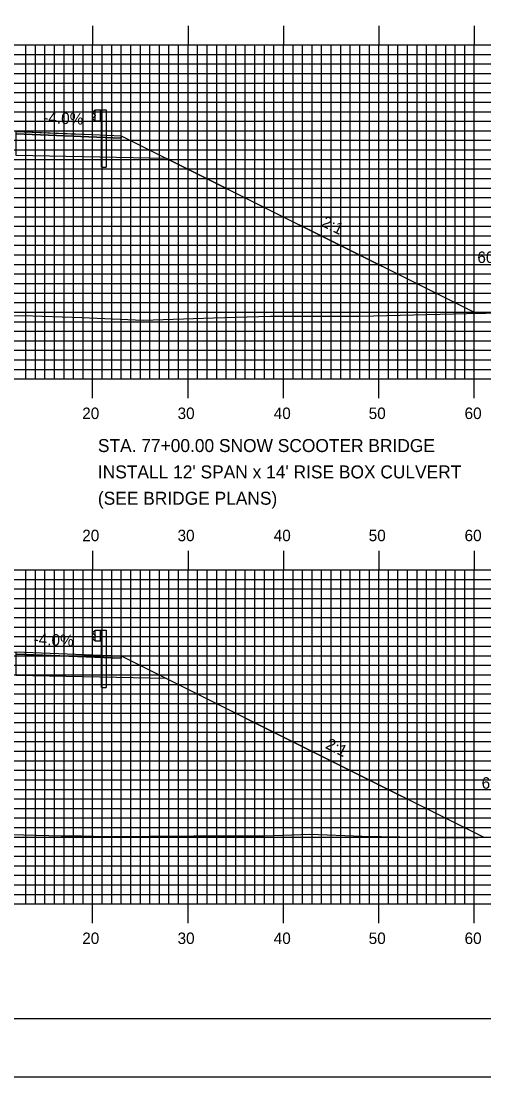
# Model space of a CAD drawing. Extents: x 1761791 to 1762134, y 442591 to 442811.
# Drawn here: x 1761969.3 to 1762017.8, y 442590.5 to 442701.2 of the extents above; entities that cross this region are included whole.
import ezdxf

# ---------------------------------------------------------------- set-up
doc = ezdxf.new("R2010")
doc.units = 0
for name, color, linetype in [('ANNOTATION', 7, 'Continuous'), ('BORDER', 7, 'Continuous'), ('D_Guardrail_Beam_Rt', 7, 'Continuous'), ('D_Roadway_Centerline', 7, 'Continuous'), ('D_Roadway_Edge_Shoulder', 7, 'Continuous'), ('D_Roadway_SlopeLines', 7, 'Continuous'), ('D_Roadway_SubGrade', 7, 'Continuous'), ('D_Text_Standard', 7, 'Continuous'), ('H_V ANNOTATION', 7, 'Continuous'), ('MAJOR', 7, 'Continuous'), ('MINOR', 7, 'Continuous'), ('PLOT BOUNDARY', 7, 'Continuous'), ('S_Roadway_Centerline', 7, 'Continuous')]:
    doc.layers.add(name, color=color, linetype=linetype)

msp = doc.modelspace()

# ---------------------------------------------------------------- linework, layer by layer
at = {"layer": 'BORDER'}
msp.add_lwpolyline([(1761807.15, 442596.67), (1762127.15, 442596.67), (1762127.15, 442806.67), (1761807.15, 442806.67)], close=True, dxfattribs=at)
at = {"layer": 'D_Guardrail_Beam_Rt'}
for p, q in [((1761976.93, 442691.75), (1761976.79, 442691.65)), ((1761977.02, 442691.77), (1761976.95, 442691.75)), ((1761977.02, 442691.85), (1761977.71, 442691.85)), ((1761977.02, 442690.68), (1761977.02, 442691.85)), ((1761977.55, 442691.85), (1761977.55, 442690.68)), ((1761977.65, 442691.85), (1761977.65, 442690.68)), ((1761977.71, 442691.85), (1761978.18, 442691.85)), ((1761977.71, 442691.85), (1761977.71, 442690.68)), ((1761978.18, 442691.85), (1761978.18, 442685.85)), ((1761976.79, 442691.5), (1761976.99, 442691.37)), ((1761976.99, 442691.17), (1761976.79, 442691.03)), ((1761976.79, 442690.89), (1761976.93, 442690.79)), ((1761976.95, 442690.78), (1761977.02, 442690.77)), ((1761977.02, 442691.3), (1761977.02, 442691.23)), ((1761977.71, 442690.68), (1761977.02, 442690.68)), ((1761977.69, 442685.85), (1761977.69, 442690.68)), ((1761977.69, 442685.85), (1761978.18, 442685.85)), ((1761977.02, 442637.35), (1761977.71, 442637.35)), ((1761977.02, 442636.18), (1761977.02, 442637.35)), ((1761977.54, 442637.35), (1761977.54, 442636.18)), ((1761977.65, 442637.35), (1761977.65, 442636.18)), ((1761977.71, 442637.35), (1761978.18, 442637.35)), ((1761977.71, 442637.35), (1761977.71, 442636.18)), ((1761978.18, 442637.35), (1761978.18, 442631.35)), ((1761976.93, 442637.25), (1761976.79, 442637.15)), ((1761976.79, 442637), (1761976.99, 442636.87)), ((1761976.99, 442636.67), (1761976.79, 442636.53)), ((1761976.79, 442636.39), (1761976.93, 442636.29)), ((1761977.02, 442637.27), (1761976.95, 442637.25)), ((1761976.95, 442636.28), (1761977.02, 442636.27)), ((1761977.02, 442636.8), (1761977.02, 442636.73)), ((1761977.71, 442636.18), (1761977.02, 442636.18)), ((1761977.69, 442631.35), (1761977.69, 442636.18)), ((1761977.69, 442631.35), (1761978.18, 442631.35))]:
    msp.add_line(p, q, dxfattribs=at)
for centre, major_axis, start_param, end_param in [((1761976.84, 442691.57), (-0.0877, 0), 5.323254, 7.243116), ((1761976.96, 442691.71), (-0.0417, 0), 4.907132, 5.323254), ((1761976.84, 442690.96), (-0.0877, 0), 5.323254, 7.243116), ((1761976.96, 442690.82), (-0.0417, 0), 0.959931, 1.376053), ((1761976.94, 442691.3), (0.0789, 0), 0, 0.959931), ((1761976.94, 442691.23), (0.0789, 0), 5.323254, 6.283185), ((1761976.84, 442637.07), (-0.0877, 0), 5.323254, 7.243116), ((1761976.84, 442636.46), (-0.0877, 0), 5.323254, 7.243116), ((1761976.96, 442637.21), (-0.0417, 0), 4.907132, 5.323254), ((1761976.96, 442636.32), (-0.0417, 0), 0.959931, 1.376053), ((1761976.94, 442636.8), (0.0789, 0), 0, 0.959931), ((1761976.94, 442636.73), (0.0789, 0), 5.323254, 6.283185)]:
    msp.add_ellipse(centre, major_axis=major_axis, ratio=0.995501, start_param=start_param, end_param=end_param, dxfattribs=at)
at = {"layer": 'D_Roadway_Centerline'}
for points in [[(1761968.76, 442689.59), (1761974.5, 442689.36), (1761976.75, 442689.27), (1761979.75, 442689.15), (1761984.5, 442686.77), (1761984.5, 442686.77), (1761984.51, 442686.77), (1761997.36, 442680.34), (1762016.93, 442670.56), (1762016.94, 442670.55)], [(1761899.44, 442616.62), (1761899.44, 442616.63), (1761910.41, 442622.11), (1761928.44, 442631.13), (1761928.46, 442631.14), (1761933.75, 442633.78), (1761935.04, 442633.83), (1761936.75, 442633.9), (1761944.75, 442634.22), (1761956.75, 442634.66), (1761956.75, 442634.66), (1761968.75, 442635.09), (1761968.75, 442635.09), (1761968.75, 442635.09), (1761976.75, 442634.77), (1761976.75, 442634.77), (1761979.75, 442634.65), (1761984.5, 442632.27), (1761984.5, 442632.27), (1762000.79, 442624.13), (1762017.75, 442615.65)]]:
    msp.add_lwpolyline(points, dxfattribs=at)
at = {"layer": 'D_Roadway_Edge_Shoulder'}
for points in [[(1761968.75, 442689.59), (1761976.75, 442689.27), (1761976.75, 442689.27), (1761979.75, 442689.15), (1761979.75, 442688.9), (1761968.75, 442689.34)], [(1761968.75, 442635.09), (1761976.75, 442634.77), (1761976.75, 442634.77), (1761979.75, 442634.65), (1761979.75, 442634.4), (1761968.75, 442634.84)]]:
    msp.add_lwpolyline(points, close=True, dxfattribs=at)
at = {"layer": 'D_Roadway_SlopeLines'}
for points in [[(1761979.75, 442689.15), (1762016.94, 442670.55)], [(1761979.75, 442634.65), (1762017.75, 442615.65)]]:
    msp.add_lwpolyline(points, dxfattribs=at)
at = {"layer": 'D_Roadway_SubGrade'}
for points in [[(1761968.75, 442688.92), (1761968.75, 442689.34), (1761979.75, 442688.9), (1761979.75, 442689.15), (1761984.5, 442686.77), (1761968.75, 442687.09)], [(1761968.75, 442634.42), (1761968.75, 442634.84), (1761979.75, 442634.4), (1761979.75, 442634.65), (1761984.5, 442632.27), (1761968.75, 442632.59)]]:
    msp.add_lwpolyline(points, close=True, dxfattribs=at)
at = {"layer": 'MAJOR'}
for p, q in [((1761976.75, 442700.67), (1761976.75, 442698.67)), ((1761986.75, 442700.67), (1761986.75, 442698.67)), ((1761996.75, 442700.67), (1761996.75, 442698.67)), ((1762006.75, 442700.67), (1762006.75, 442698.67)), ((1762016.75, 442700.67), (1762016.75, 442698.67)), ((1761816.75, 442698.67), (1762096.75, 442698.67)), ((1761816.75, 442698.67), (1762096.75, 442698.67)), ((1761976.75, 442663.67), (1761976.75, 442698.67)), ((1761986.75, 442663.67), (1761986.75, 442698.67)), ((1761996.75, 442663.67), (1761996.75, 442698.67)), ((1762006.75, 442663.67), (1762006.75, 442698.67)), ((1762016.75, 442663.67), (1762016.75, 442698.67)), ((1761816.75, 442693.67), (1762096.75, 442693.67)), ((1761816.75, 442688.67), (1762096.75, 442688.67)), ((1761816.75, 442683.67), (1762096.75, 442683.67)), ((1761816.75, 442678.67), (1762096.75, 442678.67)), ((1761816.75, 442673.67), (1762096.75, 442673.67)), ((1761816.75, 442668.67), (1762096.75, 442668.67)), ((1761816.75, 442663.67), (1762096.75, 442663.67)), ((1761816.75, 442663.67), (1762096.75, 442663.67)), ((1761976.75, 442661.66), (1761976.75, 442663.67)), ((1761986.75, 442661.66), (1761986.75, 442663.67)), ((1761996.75, 442661.66), (1761996.75, 442663.67)), ((1762006.75, 442661.66), (1762006.75, 442663.67)), ((1762016.75, 442661.66), (1762016.75, 442663.67)), ((1761976.75, 442645.67), (1761976.75, 442643.67)), ((1761986.75, 442645.67), (1761986.75, 442643.67)), ((1761996.75, 442645.67), (1761996.75, 442643.67)), ((1762006.75, 442645.67), (1762006.75, 442643.67)), ((1762016.75, 442645.67), (1762016.75, 442643.67)), ((1761816.75, 442643.67), (1762096.75, 442643.67)), ((1761816.75, 442643.67), (1762096.75, 442643.67)), ((1761976.75, 442608.67), (1761976.75, 442643.67)), ((1761986.75, 442608.67), (1761986.75, 442643.67)), ((1761996.75, 442608.67), (1761996.75, 442643.67)), ((1762006.75, 442608.67), (1762006.75, 442643.67)), ((1762016.75, 442608.67), (1762016.75, 442643.67)), ((1761816.75, 442638.67), (1762096.75, 442638.67)), ((1761816.75, 442633.67), (1762096.75, 442633.67)), ((1761816.75, 442628.67), (1762096.75, 442628.67)), ((1761816.75, 442623.67), (1762096.75, 442623.67)), ((1761816.75, 442618.67), (1762096.75, 442618.67)), ((1761816.75, 442613.67), (1762096.75, 442613.67)), ((1761816.75, 442608.67), (1762096.75, 442608.67)), ((1761816.75, 442608.67), (1762096.75, 442608.67)), ((1761976.75, 442606.66), (1761976.75, 442608.67)), ((1761986.75, 442606.66), (1761986.75, 442608.67)), ((1761996.75, 442606.66), (1761996.75, 442608.67)), ((1762006.75, 442606.66), (1762006.75, 442608.67)), ((1762016.75, 442606.66), (1762016.75, 442608.67))]:
    msp.add_line(p, q, dxfattribs=at)
at = {"layer": 'MINOR'}
for p, q in [((1761969.75, 442663.67), (1761969.75, 442698.67)), ((1761970.75, 442663.67), (1761970.75, 442698.67)), ((1761971.75, 442663.67), (1761971.75, 442698.67)), ((1761972.75, 442663.67), (1761972.75, 442698.67)), ((1761973.75, 442663.67), (1761973.75, 442698.67)), ((1761974.75, 442663.67), (1761974.75, 442698.67)), ((1761975.75, 442663.67), (1761975.75, 442698.67)), ((1761977.75, 442663.67), (1761977.75, 442698.67)), ((1761978.75, 442663.67), (1761978.75, 442698.67)), ((1761979.75, 442663.67), (1761979.75, 442698.67)), ((1761980.75, 442663.67), (1761980.75, 442698.67)), ((1761981.75, 442663.67), (1761981.75, 442698.67)), ((1761982.75, 442663.67), (1761982.75, 442698.67)), ((1761983.75, 442663.67), (1761983.75, 442698.67)), ((1761984.75, 442663.67), (1761984.75, 442698.67)), ((1761985.75, 442663.67), (1761985.75, 442698.67)), ((1761987.75, 442663.67), (1761987.75, 442698.67)), ((1761988.75, 442663.67), (1761988.75, 442698.67)), ((1761989.75, 442663.67), (1761989.75, 442698.67)), ((1761990.75, 442663.67), (1761990.75, 442698.67)), ((1761991.75, 442663.67), (1761991.75, 442698.67)), ((1761992.75, 442663.67), (1761992.75, 442698.67)), ((1761993.75, 442663.67), (1761993.75, 442698.67)), ((1761994.75, 442663.67), (1761994.75, 442698.67)), ((1761995.75, 442663.67), (1761995.75, 442698.67)), ((1761997.75, 442663.67), (1761997.75, 442698.67)), ((1761998.75, 442663.67), (1761998.75, 442698.67)), ((1761999.75, 442663.67), (1761999.75, 442698.67)), ((1762000.75, 442663.67), (1762000.75, 442698.67)), ((1762001.75, 442663.67), (1762001.75, 442698.67)), ((1762002.75, 442663.67), (1762002.75, 442698.67)), ((1762003.75, 442663.67), (1762003.75, 442698.67)), ((1762004.75, 442663.67), (1762004.75, 442698.67)), ((1762005.75, 442663.67), (1762005.75, 442698.67)), ((1762007.75, 442663.67), (1762007.75, 442698.67)), ((1762008.75, 442663.67), (1762008.75, 442698.67)), ((1762009.75, 442663.67), (1762009.75, 442698.67)), ((1762010.75, 442663.67), (1762010.75, 442698.67)), ((1762011.75, 442663.67), (1762011.75, 442698.67)), ((1762012.75, 442663.67), (1762012.75, 442698.67)), ((1762013.75, 442663.67), (1762013.75, 442698.67)), ((1762014.75, 442663.67), (1762014.75, 442698.67)), ((1762015.75, 442663.67), (1762015.75, 442698.67)), ((1761816.75, 442697.67), (1762096.75, 442697.67)), ((1761816.75, 442696.67), (1762096.75, 442696.67)), ((1761816.75, 442695.67), (1762096.75, 442695.67)), ((1761816.75, 442694.67), (1762096.75, 442694.67)), ((1761816.75, 442692.67), (1762096.75, 442692.67)), ((1761816.75, 442691.67), (1762096.75, 442691.67)), ((1761816.75, 442690.67), (1762096.75, 442690.67)), ((1761816.75, 442689.67), (1762096.75, 442689.67)), ((1761816.75, 442687.67), (1762096.75, 442687.67)), ((1761816.75, 442686.67), (1762096.75, 442686.67)), ((1761816.75, 442685.67), (1762096.75, 442685.67)), ((1761816.75, 442684.67), (1762096.75, 442684.67)), ((1761816.75, 442682.67), (1762096.75, 442682.67)), ((1761816.75, 442681.67), (1762096.75, 442681.67)), ((1761816.75, 442680.67), (1762096.75, 442680.67)), ((1761816.75, 442679.67), (1762096.75, 442679.67)), ((1761816.75, 442677.67), (1762096.75, 442677.67)), ((1761816.75, 442676.67), (1762096.75, 442676.67)), ((1761816.75, 442675.67), (1762096.75, 442675.67)), ((1761816.75, 442674.67), (1762096.75, 442674.67)), ((1761816.75, 442672.67), (1762096.75, 442672.67)), ((1761816.75, 442671.67), (1762096.75, 442671.67)), ((1761816.75, 442670.67), (1762096.75, 442670.67)), ((1761816.75, 442669.67), (1762096.75, 442669.67)), ((1761816.75, 442667.67), (1762096.75, 442667.67)), ((1761816.75, 442666.67), (1762096.75, 442666.67)), ((1761816.75, 442665.67), (1762096.75, 442665.67)), ((1761816.75, 442664.67), (1762096.75, 442664.67)), ((1761969.75, 442608.67), (1761969.75, 442643.67)), ((1761970.75, 442608.67), (1761970.75, 442643.67)), ((1761971.75, 442608.67), (1761971.75, 442643.67)), ((1761972.75, 442608.67), (1761972.75, 442643.67)), ((1761973.75, 442608.67), (1761973.75, 442643.67)), ((1761974.75, 442608.67), (1761974.75, 442643.67)), ((1761975.75, 442608.67), (1761975.75, 442643.67)), ((1761977.75, 442608.67), (1761977.75, 442643.67)), ((1761978.75, 442608.67), (1761978.75, 442643.67)), ((1761979.75, 442608.67), (1761979.75, 442643.67)), ((1761980.75, 442608.67), (1761980.75, 442643.67)), ((1761981.75, 442608.67), (1761981.75, 442643.67)), ((1761982.75, 442608.67), (1761982.75, 442643.67)), ((1761983.75, 442608.67), (1761983.75, 442643.67)), ((1761984.75, 442608.67), (1761984.75, 442643.67)), ((1761985.75, 442608.67), (1761985.75, 442643.67)), ((1761987.75, 442608.67), (1761987.75, 442643.67)), ((1761988.75, 442608.67), (1761988.75, 442643.67)), ((1761989.75, 442608.67), (1761989.75, 442643.67)), ((1761990.75, 442608.67), (1761990.75, 442643.67)), ((1761991.75, 442608.67), (1761991.75, 442643.67)), ((1761992.75, 442608.67), (1761992.75, 442643.67)), ((1761993.75, 442608.67), (1761993.75, 442643.67)), ((1761994.75, 442608.67), (1761994.75, 442643.67)), ((1761995.75, 442608.67), (1761995.75, 442643.67)), ((1761997.75, 442608.67), (1761997.75, 442643.67)), ((1761998.75, 442608.67), (1761998.75, 442643.67)), ((1761999.75, 442608.67), (1761999.75, 442643.67)), ((1762000.75, 442608.67), (1762000.75, 442643.67)), ((1762001.75, 442608.67), (1762001.75, 442643.67)), ((1762002.75, 442608.67), (1762002.75, 442643.67)), ((1762003.75, 442608.67), (1762003.75, 442643.67)), ((1762004.75, 442608.67), (1762004.75, 442643.67)), ((1762005.75, 442608.67), (1762005.75, 442643.67)), ((1762007.75, 442608.67), (1762007.75, 442643.67)), ((1762008.75, 442608.67), (1762008.75, 442643.67)), ((1762009.75, 442608.67), (1762009.75, 442643.67)), ((1762010.75, 442608.67), (1762010.75, 442643.67)), ((1762011.75, 442608.67), (1762011.75, 442643.67)), ((1762012.75, 442608.67), (1762012.75, 442643.67)), ((1762013.75, 442608.67), (1762013.75, 442643.67)), ((1762014.75, 442608.67), (1762014.75, 442643.67)), ((1762015.75, 442608.67), (1762015.75, 442643.67)), ((1761816.75, 442642.67), (1762096.75, 442642.67)), ((1761816.75, 442641.67), (1762096.75, 442641.67)), ((1761816.75, 442640.67), (1762096.75, 442640.67)), ((1761816.75, 442639.67), (1762096.75, 442639.67)), ((1761816.75, 442637.67), (1762096.75, 442637.67)), ((1761816.75, 442636.67), (1762096.75, 442636.67)), ((1761816.75, 442635.67), (1762096.75, 442635.67)), ((1761816.75, 442634.67), (1762096.75, 442634.67)), ((1761816.75, 442632.67), (1762096.75, 442632.67)), ((1761816.75, 442631.67), (1762096.75, 442631.67)), ((1761816.75, 442630.67), (1762096.75, 442630.67)), ((1761816.75, 442629.67), (1762096.75, 442629.67)), ((1761816.75, 442627.67), (1762096.75, 442627.67)), ((1761816.75, 442626.67), (1762096.75, 442626.67)), ((1761816.75, 442625.67), (1762096.75, 442625.67)), ((1761816.75, 442624.67), (1762096.75, 442624.67)), ((1761816.75, 442622.67), (1762096.75, 442622.67)), ((1761816.75, 442621.67), (1762096.75, 442621.67)), ((1761816.75, 442620.67), (1762096.75, 442620.67)), ((1761816.75, 442619.67), (1762096.75, 442619.67)), ((1761816.75, 442617.67), (1762096.75, 442617.67)), ((1761816.75, 442616.67), (1762096.75, 442616.67)), ((1761816.75, 442615.67), (1762096.75, 442615.67)), ((1761816.75, 442614.67), (1762096.75, 442614.67)), ((1761816.75, 442612.67), (1762096.75, 442612.67)), ((1761816.75, 442611.67), (1762096.75, 442611.67)), ((1761816.75, 442610.67), (1762096.75, 442610.67)), ((1761816.75, 442609.67), (1762096.75, 442609.67))]:
    msp.add_line(p, q, dxfattribs=at)
at = {"layer": 'PLOT BOUNDARY'}
msp.add_lwpolyline([(1761790.97, 442590.55), (1762130.97, 442590.55), (1762130.97, 442810.55), (1761790.97, 442810.55)], close=True, dxfattribs=at)
at = {"layer": 'S_Roadway_Centerline'}
for points in [[(1761884.22, 442670.83), (1761889.89, 442670.77), (1761897.56, 442670.69), (1761901.95, 442670.63), (1761904.94, 442670.56), (1761912.74, 442670.4), (1761914.03, 442670.35), (1761924.01, 442670.14), (1761933.4, 442669.91), (1761934.73, 442669.95), (1761936.47, 442669.91), (1761947.44, 442669.99), (1761955.4, 442669.9), (1761963.08, 442670.12), (1761969.44, 442670.32), (1761975.6, 442670.1), (1761982.06, 442669.84), (1761989.42, 442670.08), (1761992.96, 442670.18), (1761995.4, 442670.25), (1762004.77, 442670.23), (1762015.95, 442670.54), (1762027.87, 442670.75)], [(1761888.3, 442616.86), (1761896.19, 442616.69), (1761901.59, 442616.58), (1761907.67, 442616.49), (1761915.17, 442616.47), (1761919.6, 442616.53), (1761923.29, 442616.42), (1761941.05, 442615.94), (1761942.42, 442615.89), (1761943.47, 442615.91), (1761951.47, 442616.34), (1761952.07, 442616.37), (1761952.15, 442616.37), (1761952.25, 442616.37), (1761973.48, 442615.81), (1761975.59, 442615.79), (1761978.13, 442615.74), (1761987.37, 442615.8), (1761994.75, 442615.81), (1761999.51, 442615.98), (1762005.01, 442615.76), (1762014.87, 442615.6), (1762021.59, 442615.71)]]:
    msp.add_lwpolyline(points, dxfattribs=at)

# ---------------------------------------------------------------- texts
at = {"layer": 'ANNOTATION'}
for s, rotation, p in [('-4.0%', 357.7092, (1761971.56, 442690.47)), ('2:1', 333.4339, (1762000.65, 442679.73)), ('-4.0%', 357.7095, (1761970.55, 442635.82)), ('2:1', 333.4347, (1762001.06, 442625.03))]:
    msp.add_text(s, height=1.2, rotation=rotation, dxfattribs=at).set_placement(p)
for s, p in [('STA. 77+00.00 SNOW SCOOTER BRIDGE', (1761977.3, 442656.01)), ("INSTALL 12' SPAN x 14' RISE BOX CULVERT", (1761977.3, 442653.25)), ('(SEE BRIDGE PLANS)', (1761977.3, 442650.49))]:
    msp.add_text(s, height=1.36, dxfattribs=at).set_placement(p)
at = {"layer": 'D_Text_Standard'}
for s, p in [("60.2'", (1762017.07, 442675.82)), ("61.0'", (1762017.52, 442620.74))]:
    msp.add_text(s, height=1.2, dxfattribs=at).set_placement(p)
at = {"layer": 'H_V ANNOTATION'}
for s, p in [('20', (1761975.66, 442659.47)), ('30', (1761985.65, 442659.47)), ('40', (1761995.73, 442659.47)), ('50', (1762005.68, 442659.47)), ('60', (1762015.73, 442659.47)), ('20', (1761975.66, 442646.67)), ('30', (1761985.65, 442646.67)), ('40', (1761995.73, 442646.67)), ('50', (1762005.68, 442646.67)), ('60', (1762015.73, 442646.67)), ('20', (1761975.66, 442604.47)), ('30', (1761985.65, 442604.47)), ('40', (1761995.73, 442604.47)), ('50', (1762005.68, 442604.47)), ('60', (1762015.73, 442604.47))]:
    msp.add_text(s, height=1.2, dxfattribs=at).set_placement(p)

doc.saveas('drawing.dxf')
